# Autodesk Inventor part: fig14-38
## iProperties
Created: 2005-03
Part Number: fig14-38
Document SubType Name: Sheet Metal
Designer: CADCIM
Manufacturer: Standard
Standards Organization: Custom
Author: CADCIM
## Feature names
1. Plate1
2. Plate2
3. Bend1
4. Plate4
5. Bend3
6. Cut1
